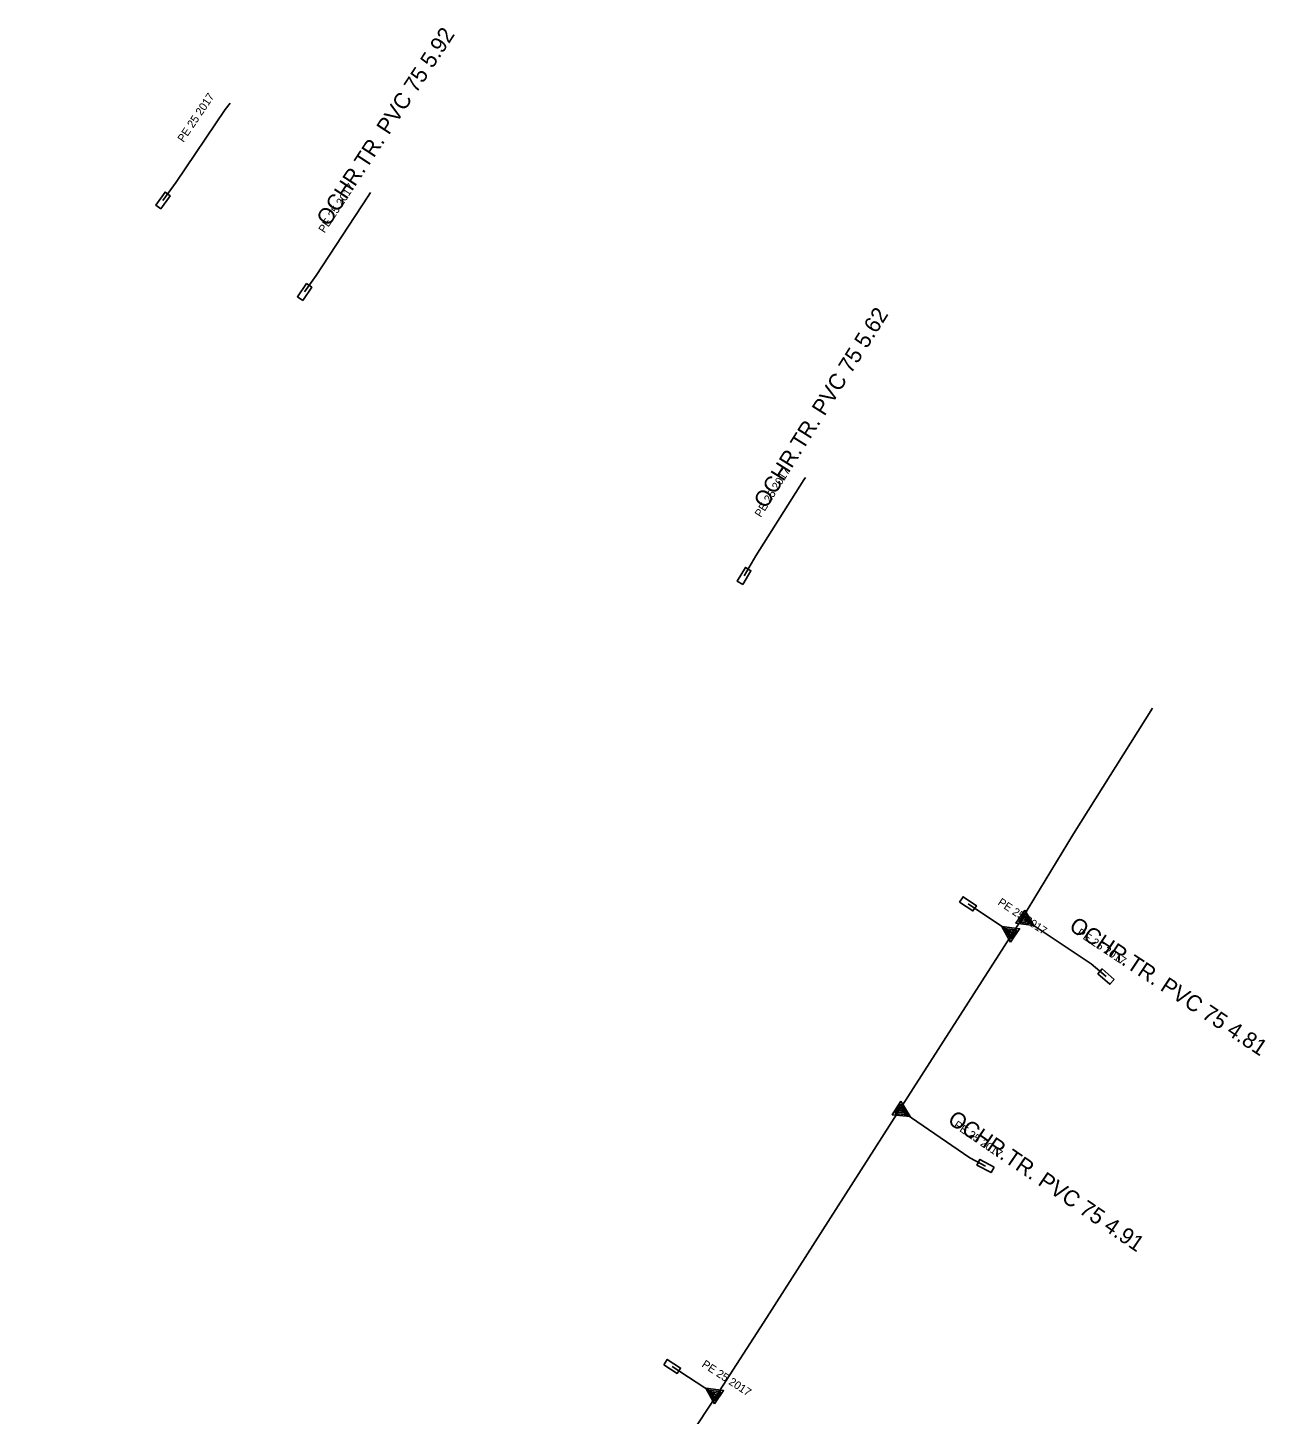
# Model space of a CAD drawing. Extents: x -742724 to -742460, y -1054602 to -1054379.
# Drawn here: x -742613.1 to -742535.8, y -1054485.6 to -1054399 of the extents above; entities that cross this region are included whole.
import ezdxf

# ---------------------------------------------------------------- set-up
doc = ezdxf.new("R2010")
doc.units = 0
for name, color, linetype in [('ST OP Chráni_ka - provoz', 7, 'Continuous'), ('ST Úsek p_ípojky - provoz', 7, 'Continuous'), ('ST Úsek plynovodu - provoz', 7, 'Continuous'), ('Vrstva 1', 7, 'Continuous')]:
    doc.layers.add(name, color=color, linetype=linetype)

msp = doc.modelspace()

# ---------------------------------------------------------------- linework, layer by layer
at = {"layer": 'ST OP Chráni_ka - provoz'}
for points in [[(-742600.75, -1054404.08), (-742603.81, -1054408.62)], [(-742591.82, -1054409.5), (-742595.07, -1054414.45)], [(-742564.6, -1054427.22), (-742567.59, -1054431.98)], [(-742550.64, -1054454.8), (-742546.63, -1054457.46)], [(-742558.26, -1054466.82), (-742554.21, -1054469.59)]]:
    msp.add_lwpolyline(points, dxfattribs=at)
at = {"layer": 'ST Úsek p_ípojky - provoz'}
for points in [[(-742600.43, -1054403.67), (-742600.75, -1054404.08), (-742603.81, -1054408.62), (-742604.639, -1054409.762)], [(-742591.665, -1054409.259), (-742591.82, -1054409.5), (-742595.07, -1054414.45), (-742595.787, -1054415.478)], [(-742564.491, -1054427.067), (-742564.6, -1054427.22), (-742567.59, -1054431.98), (-742568.325, -1054433.229)], [(-742551.807, -1054455.412), (-742554.332, -1054453.722)], [(-742550.937, -1054454.601), (-742550.64, -1054454.8)], [(-742550.64, -1054454.8), (-742546.63, -1054457.46), (-742545.705, -1054458.27)], [(-742551.56, -1054455.58), (-742551.807, -1054455.412)], [(-742558.618, -1054466.593), (-742558.373, -1054466.748)], [(-742558.373, -1054466.748), (-742558.26, -1054466.82), (-742554.21, -1054469.59), (-742553.241, -1054470.108)], [(-742570.299, -1054484.274), (-742572.82, -1054482.63)], [(-742570.052, -1054484.442), (-742570.299, -1054484.274)]]:
    msp.add_lwpolyline(points, dxfattribs=at)
at = {"layer": 'ST Úsek plynovodu - provoz'}
msp.add_lwpolyline([(-742542.794, -1054441.484), (-742547.74, -1054449.35), (-742550.937, -1054454.601), (-742551.56, -1054455.58), (-742558.618, -1054466.593), (-742566.909, -1054479.579), (-742570.052, -1054484.442), (-742573.419, -1054489.574), (-742578.87, -1054497.975), (-742585.21, -1054507.86), (-742586.36, -1054509.61), (-742592.8, -1054519.64), (-742598.492, -1054528.841), (-742598.702, -1054529.158), (-742599.1, -1054529.76), (-742605.67, -1054539.71), (-742611, -1054547.54), (-742613.09, -1054550.51)], dxfattribs=at)
at = {"layer": 'Vrstva 1'}
for points in [[(-742604.771, -1054410.284), (-742605.095, -1054410.049), (-742604.507, -1054409.24), (-742604.183, -1054409.475)], [(-742595.909, -1054416.003), (-742596.237, -1054415.774), (-742595.665, -1054414.953), (-742595.337, -1054415.182)], [(-742568.406, -1054433.761), (-742568.751, -1054433.558), (-742568.244, -1054432.697), (-742567.899, -1054432.9)], [(-742554.859, -1054453.61), (-742554.636, -1054453.278), (-742553.805, -1054453.834), (-742554.028, -1054454.166)], [(-742550.777, -1054454.106), (-742551.334, -1054454.937), (-742550.225, -1054455.078)], [(-742551.16, -1054454.858), (-742550.411, -1054454.954), (-742550.784, -1054454.297)], [(-742551.675, -1054456.107), (-742551.112, -1054455.28), (-742552.22, -1054455.131)], [(-742551.286, -1054455.357), (-742552.035, -1054455.257), (-742551.666, -1054455.916)], [(-742550.596, -1054454.829), (-742550.791, -1054454.487), (-742550.988, -1054454.78)], [(-742551.851, -1054455.382), (-742551.658, -1054455.726), (-742551.459, -1054455.434)], [(-742545.197, -1054458.449), (-742545.461, -1054458.75), (-742546.213, -1054458.091), (-742545.949, -1054457.79)], [(-742558.528, -1054466.058), (-742559.063, -1054466.903), (-742557.95, -1054467.015)], [(-742558.892, -1054466.82), (-742558.14, -1054466.896), (-742558.53, -1054466.249)], [(-742558.328, -1054466.776), (-742558.532, -1054466.439), (-742558.721, -1054466.737)], [(-742552.706, -1054470.167), (-742552.894, -1054470.52), (-742553.776, -1054470.049), (-742553.588, -1054469.696)], [(-742573.348, -1054482.524), (-742573.13, -1054482.189), (-742572.292, -1054482.736), (-742572.51, -1054483.071)], [(-742570.167, -1054484.969), (-742569.604, -1054484.142), (-742570.712, -1054483.993)], [(-742569.778, -1054484.219), (-742570.527, -1054484.119), (-742570.158, -1054484.778)], [(-742570.343, -1054484.244), (-742570.15, -1054484.588), (-742569.951, -1054484.296)]]:
    msp.add_lwpolyline(points, close=True, dxfattribs=at)

# ---------------------------------------------------------------- texts
at = {"layer": 'ST OP Chráni_ka - provoz'}
for s, rotation, p in [('OCHR.TR. PVC 75 5.92', 56.71247, (-742594.281, -1054411.426)), ('OCHR.TR. PVC 75 5.62', 57.86496, (-742566.942, -1054429.068)), ('OCHR.TR. PVC 75 4.81', 326.44203, (-742548.082, -1054455.297)), ('OCHR.TR. PVC 75 4.91', 325.6298, (-742555.67, -1054467.38))]:
    msp.add_text(s, height=1, rotation=rotation, dxfattribs=at).set_placement(p)
at = {"layer": 'ST Úsek p_ípojky - provoz'}
for rotation, p in [(56.01968, (-742603.358, -1054406.161)), (56.71247, (-742594.546, -1054411.83)), (57.86496, (-742567.277, -1054429.602)), (326.20533, (-742552.513, -1054453.736)), (326.44203, (-742547.57, -1054455.637)), (325.6298, (-742555.272, -1054467.652)), (326.89074, (-742571.013, -1054482.614))]:
    msp.add_text('PE 25 2017', height=0.5, rotation=rotation, dxfattribs=at).set_placement(p)

doc.saveas('drawing.dxf')
